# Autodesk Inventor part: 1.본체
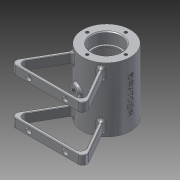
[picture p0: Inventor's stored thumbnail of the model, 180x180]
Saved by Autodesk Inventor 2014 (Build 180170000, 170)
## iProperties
Created: 2016-03
Part Number: 1.본체
Material: 알루미늄 6061
Document SubType Name: Modeling
Designer: 406-0077
Density: 2.71 g/cm^3
Appearance: 알루미늄 - 평지
Author: 406-0077
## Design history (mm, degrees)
sketch "스케치1"
  geometry: C1 r 26 at (0, 0); 1 further point
  constraints: 1 centre point, 1 coincident
  dimensions: "d0" = 52 diameter of C1
extrude "돌출1" new body sketch "스케치1" distance "d1" = 70; taper "d2" = 0 deg
sketch "스케치2"
  geometry: L1 (-26, -70)-(26, -70) reference; L2 (0, 0)-(0, -70); L3 (-26, 0)-(26, 0) reference; L4 (16, 0)-(16, -12); L5 (16, -12)-(14, -12); L6 (14, -12)-(14, -14); L7 (14, -14)-(21, -14); L8 (21, -14)-(21, -56); L9 (21, -56)-(14, -56); L10 (14, -56)-(14, -58); L11 (14, -58)-(16, -58); L12 (16, -58)-(16, -70)
  constraints: 20 end point, 5 perpendicular, 4 parallel, 2 point on line, 1 midpoint
  dimensions: "d3" = 32 diameter of L4 L2; "d4" = 28 diameter of L6 L2; "d5" = 42 diameter of L8 L2; "d6" = 28 diameter of L10 L2; "d7" = 32 diameter of L12 L2; "d8" = 12 distance of L4.start L4.end; "d9" = 42 distance of L7.end L8.end; "d10" = 12 distance of L11.end L12.end; "d11" = 2 distance of L9.end L10.end
revolve "회전1" sketch "스케치2" stored, may be unused: angle "d12" = 90 deg
fillet "모깎기1" dims "d13" = 0.3
chamfer "모따기1" distance "d14" = 1; stored, may be unused: second distance "d15" = 2, angle "d16" = 45 deg
fillet "모깎기2" dims "d17" = 3
node "작업 평면1"
sketch "스케치3"
  geometry: L1 (-16.613, -20)-(-38.264, -57.5); L2 (-33.934, -65)-(33.934, -65); L3 (38.264, -57.5)-(16.613, -20); L4 (0, 26)-(0, -65); L5 (-14.183, -21.791)-(-33.068, -54.5); L6 (-28.738, -62)-(28.738, -62); L7 (33.068, -54.5)-(14.183, -21.791); A1 r 26 centre (0, 0) between (-16.613, -20) and (16.613, -20) reference; A2 r 5 centre (-33.934, -60) between (-38.264, -57.5) and (-33.934, -65); A3 r 5 centre (-28.738, -57) between (-33.068, -54.5) and (-28.738, -62); A4 r 5 centre (28.738, -57) between (28.738, -62) and (33.068, -54.5); A5 r 5 centre (33.934, -60) between (33.934, -65) and (38.264, -57.5); 1 further point
  constraints: 14 end point, 13 point on circle, 8 tangent, 4 centre point, 3 equal radius, 1 horizontal, 1 midpoint, 1 perpendicular, 1 point on line, 1 other
  dimensions: "d19" = 30 deg angle of L4 L1; "d20" = 3 distance between parallel lines of L1 L5; "d21" = 5 radius of A2; "d23" = 65 distance from line of L2 point (0, 0); "d24" = 45 distance from line of L2 L3.end; "d25" = 3 distance between parallel lines of L2 L6; "d26" = 3 distance between parallel lines of L3 L7
extrude "돌출2" join sketch "스케치3" distance "d27" = 10; taper "d28" = 0 deg
node "작업 평면2"
node "작업 평면3"
sketch "스케치4"
  geometry: L1 (-26, 0)-(26, 0) reference; L2 (-26, -70)-(26, -70) reference; L3 (0, 0)-(0, -70); C1 r 5 at (0, -35)
  constraints: 2 end point, 2 midpoint, 1 centre point
  dimensions: "d30" = 10 diameter of C1
extrude "돌출3" join sketch "스케치4" stored distance "d31" = 10; taper "d32" = 0 deg
sketch "스케치6"
  geometry: C1 r 5 at (0, 0) reference; 5 further points
  constraints: 4 coincident
hole "구멍1" sketch "스케치6" at (0, 0) diameter "d33" = 5.188; stored, may be unused: countersink angle "d37" = 90 deg, drill point angle "d39" = 118 deg; dims "d34" = 14, "d35" = 4, "d36" = 2, "d38" = 15
sketch "스케치7"
  geometry: L1 (0, 0)-(67.868, 0) reference; L2 (67.868, -10)-(0, -10) reference; L3 (33.934, 0)-(33.934, -10); C1 r 3 at (13.934, -5); C2 r 3 at (53.934, -5); 1 further point
  constraints: 2 centre point, 2 end point, 2 midpoint
  dimensions: "d40" = 6 diameter of C1; "d41" = 6 diameter of C2; "d43" = 5 distance from line of L1 C1.centre; "d44" = 5 distance from line of L1 C2.centre; "d90" = 40 distance of C2.centre C1.centre; "d91" = 20 distance from line of C1.centre L3
extrude "돌출4" cut sketch "스케치7" distance "d46" = 10; taper "d47" = 0 deg
fillet "모깎기3" dims "d48" = 2
sketch "스케치9"
  geometry: L1 (0, 0)-(0, -26); L2 (0, 0)-(-6.729, -25.114); A1 r 26 centre (0, 0) between (0, -26) and (-6.729, -25.114) reference
  constraints: 4 end point, 2 point on circle, 1 vertical
  dimensions: "d63" = 15 deg angle of L1 L2
node "작업 평면7"
sketch "스케치13"
  geometry: C1 r 6 at (0, 0); 1 further point
  constraints: 1 centre point
  dimensions: "d65" = 12 diameter of C1; "d66" = 35 distance of point (0, 35) C1.centre
extrude "돌출6" join sketch "스케치13" stored distance "d67" = 10; taper "d68" = 0 deg
sketch "스케치14"
  geometry: C1 r 6 at (0, 0) reference; 2 further points
  constraints: 1 coincident
hole "구멍3" sketch "스케치14" at (0, 0) diameter "d69" = 5.188; stored, may be unused: countersink angle "d73" = 90 deg, drill point angle "d75" = 118 deg; dims "d70" = 14, "d71" = 4, "d72" = 2, "d74" = 15
sketch "스케치15"
  geometry: C1 r 26 at (0, 0) reference; C2 r 17 at (0, 0) reference; A1 r 21 centre (0, 0) between (0, 21) and (21, 0); 2 further points
  constraints: 4 point on circle, 2 horizontal alignment, 2 vertical alignment, 1 centre point, 1 coincident
  dimensions: "d76" = 42 diameter of A1
hole "구멍4" sketch "스케치15" at (0, 21), (21, 0), (0, -21), (-21, 0) diameter "d77" = 3.242; stored, may be unused: countersink angle "d81" = 90 deg, drill point angle "d83" = 118 deg; dims "d78" = 8, "d79" = 4, "d80" = 2, "d82" = 10
fillet "모깎기4" dims "d84" = 2
fillet "모깎기5" dims "d85" = 0.5
fillet "모깎기6" dims "d86" = 3
node "작업 평면8"
sketch "스케치16"
  geometry: L1 (0, 0)-(0, -70); L2 (-26, -70)-(26, -70) reference; 1 further point
  constraints: 2 end point, 2 midpoint, 1 vertical, 1 other
  dimensions: "d87" = 35 distance from line of point (0, -35) L2
feature "엠보싱1" sketch "스케치16" dims "d1" = 70, "d13" = 0.3, "d88" = 0.5, "d89" = 0
node "솔리드1"
mirror "대칭1"
mirror "대칭2"
mirror "대칭5"
other parameters: "d18" = -5, "d29" = 29
